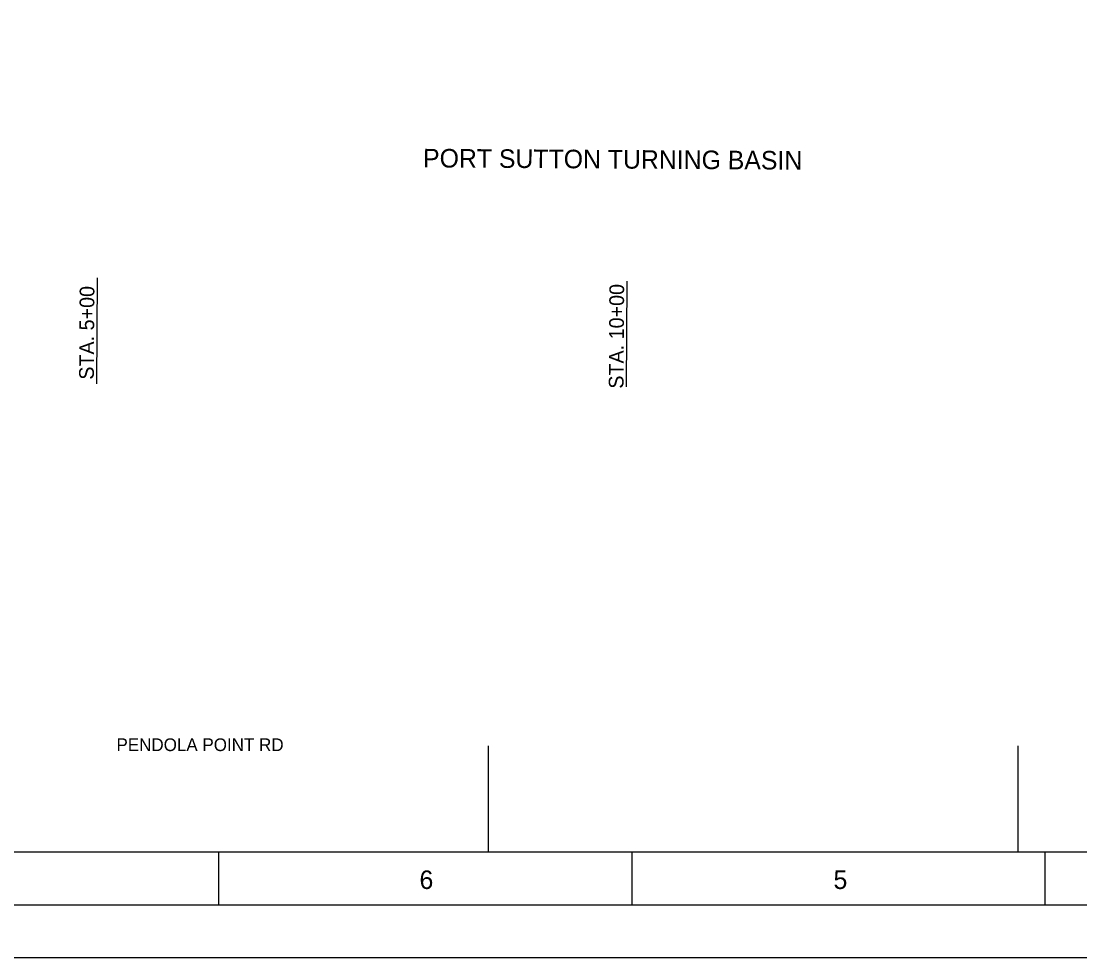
# Model space of a CAD drawing. Extents: x 515010 to 519411, y 1296833 to 1300233.
# Drawn here: x 516559 to 517558, y 1296833 to 1297717 of the extents above; entities that cross this region are included whole.
import ezdxf

# ---------------------------------------------------------------- set-up
doc = ezdxf.new("R2010")
doc.units = 0
for name, color, linetype in [('G-ANNO-NPLT', 7, 'Continuous'), ('G-ANNO-TTLB', 7, 'Continuous'), ('V-ALGN-TEXT', 7, 'Continuous'), ('V-CHAN-CNTR-IDEN', 7, 'Continuous'), ('V-ROAD-IDEN', 7, 'Continuous'), ('V-TOPO-COOR-STAT', 7, 'Continuous')]:
    doc.layers.add(name, color=color, linetype=linetype)

msp = doc.modelspace()

# ---------------------------------------------------------------- linework, layer by layer
at = {"layer": 'G-ANNO-NPLT'}
msp.add_lwpolyline([(515010.45, 1300232.97), (519410.42, 1300232.97), (519410.42, 1296832.99), (515010.45, 1296832.99)], close=True, dxfattribs=at)
at = {"layer": 'G-ANNO-TTLB'}
for p, q in [((516745.44, 1296882.99), (516745.44, 1296932.99)), ((517135.44, 1296882.99), (517135.44, 1296932.99)), ((517525.44, 1296882.99), (517525.44, 1296932.99))]:
    msp.add_line(p, q, dxfattribs=at)
for points in [[(515060.45, 1296882.99), (519360.42, 1296882.99), (519360.42, 1300182.97), (515060.45, 1300182.97)], [(519310.42, 1300132.97), (515185.45, 1300132.97), (515185.45, 1296932.99), (519310.42, 1296932.99)]]:
    msp.add_lwpolyline(points, close=True, dxfattribs=at)
at = {"layer": 'V-ALGN-TEXT'}
for p, q in [((516630.15, 1297375.05), (516630.76, 1297475.05)), ((517130.14, 1297372), (517130.75, 1297472))]:
    msp.add_line(p, q, dxfattribs=at)
at = {"layer": 'V-TOPO-COOR-STAT'}
for p, q in [((517000, 1296932.99), (517000, 1297032.99)), ((517500, 1296932.99), (517500, 1297032.99))]:
    msp.add_line(p, q, dxfattribs=at)

# ---------------------------------------------------------------- texts
at = {"layer": 'G-ANNO-TTLB'}
for s, p in [('6', (516934.77, 1296897.98)), ('5', (517325.58, 1296897.98))]:
    msp.add_text(s, height=17.5, dxfattribs=at).set_placement(p)
at = {"layer": 'V-ALGN-TEXT'}
for s, p in [('STA. 5+00', (516627.39, 1297378.8)), ('STA. 10+00', (517127.35, 1297370.34))]:
    msp.add_text(s, height=13.92, rotation=89.65035, dxfattribs=at).set_placement(p)
at = {"layer": 'V-CHAN-CNTR-IDEN'}
msp.add_text('PORT SUTTON TURNING BASIN', height=17.52, rotation=359.65012, dxfattribs=at).set_placement((516938.1, 1297579.3))
at = {"layer": 'V-ROAD-IDEN'}
msp.add_text('PENDOLA POINT RD', height=12, dxfattribs=at).set_placement((516648.71, 1297028.19))

doc.saveas('drawing.dxf')
